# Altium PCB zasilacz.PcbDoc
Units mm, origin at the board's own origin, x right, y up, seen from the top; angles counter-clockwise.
Board outline 105.03 x 79.76 mm, 2 copper layers (Top Layer, Bottom Layer); 33 components, 30 nets, 109 pads, 1 vias.
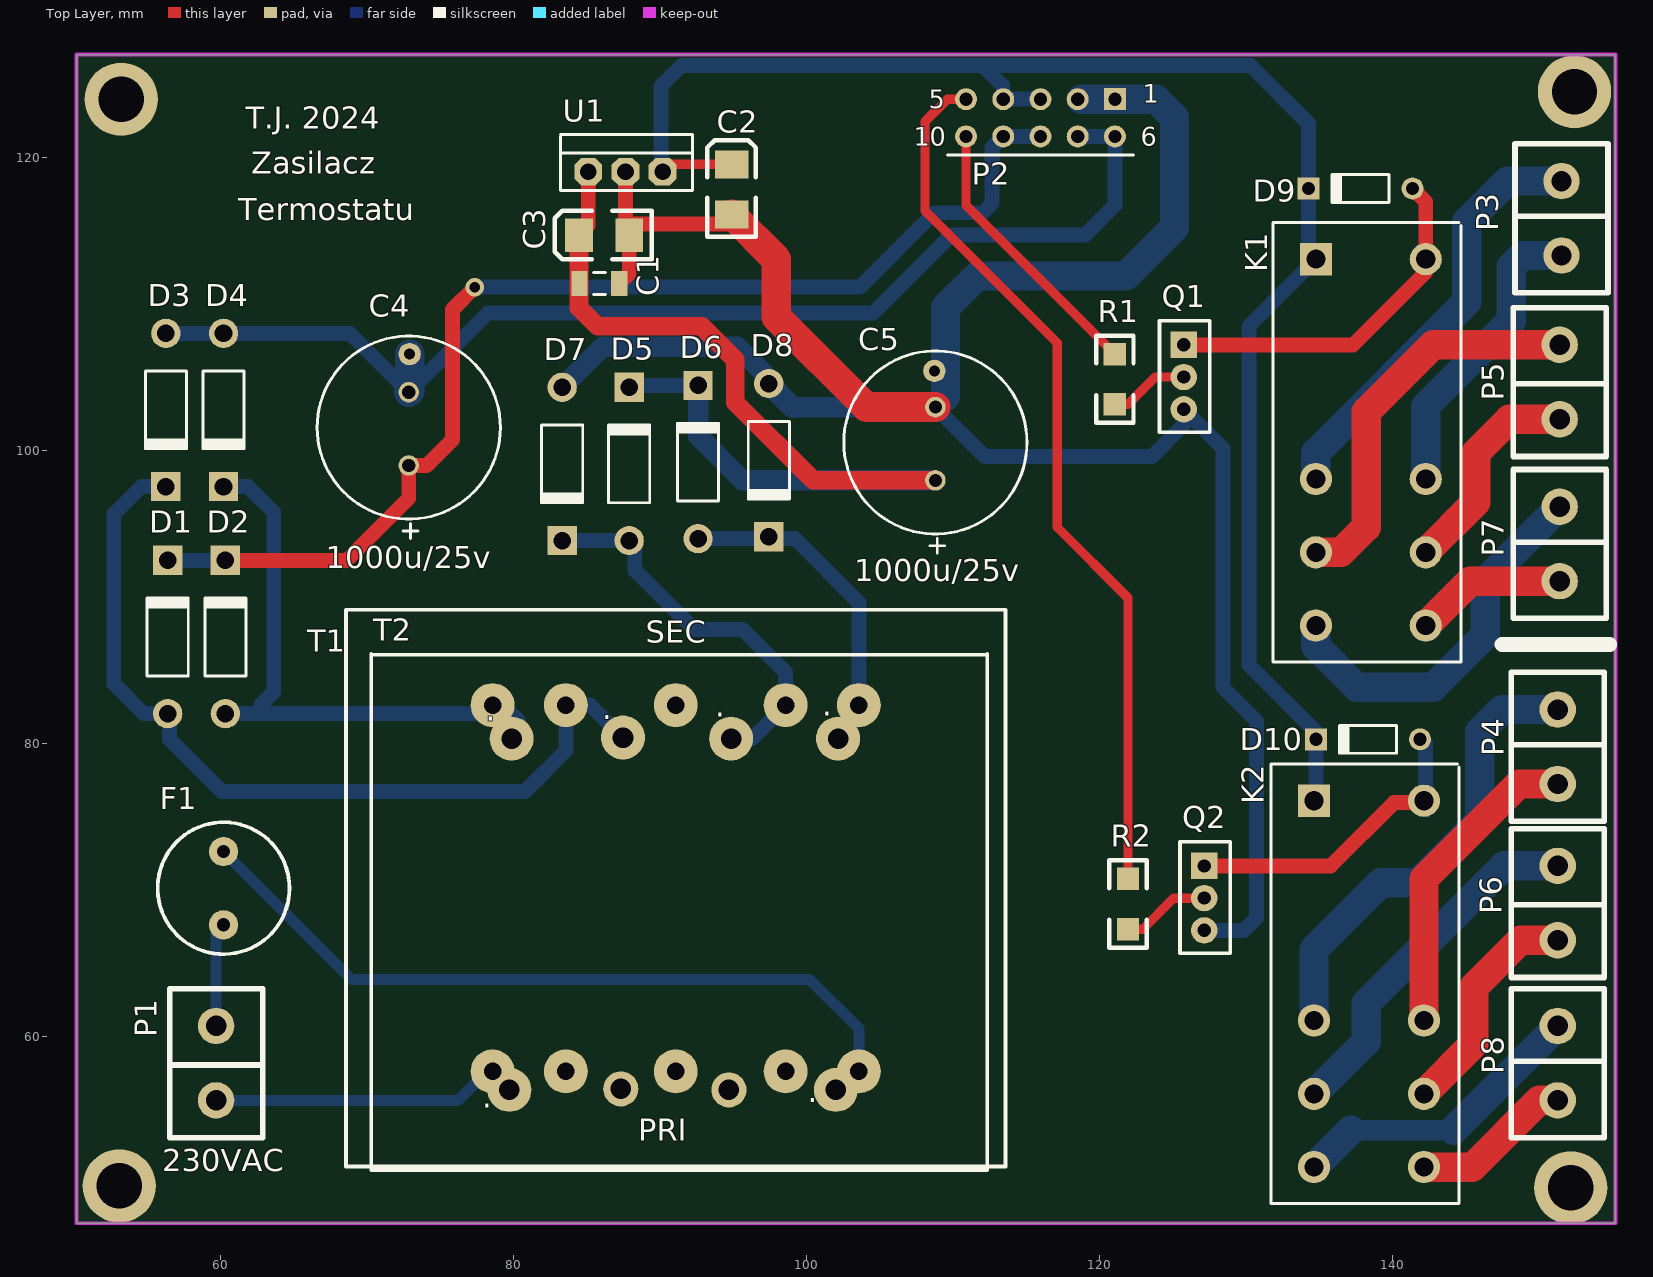
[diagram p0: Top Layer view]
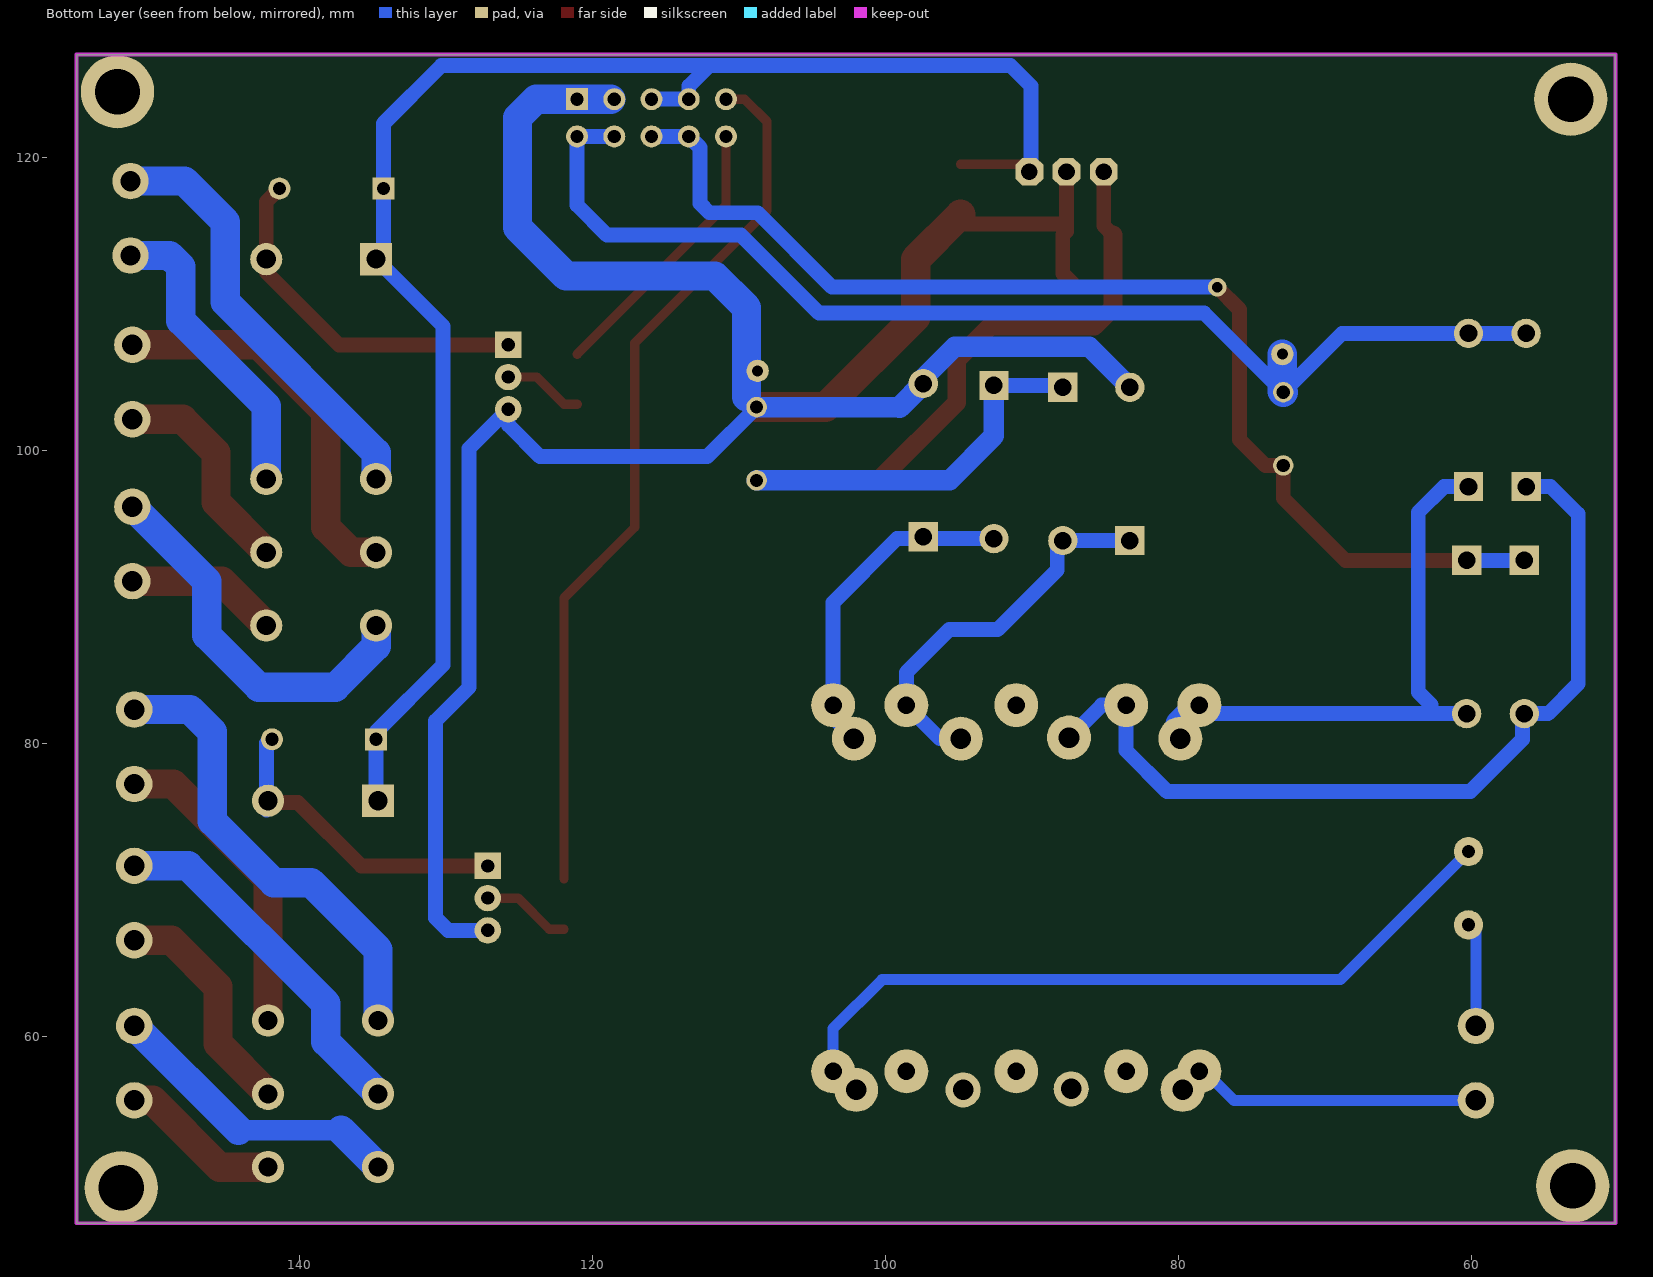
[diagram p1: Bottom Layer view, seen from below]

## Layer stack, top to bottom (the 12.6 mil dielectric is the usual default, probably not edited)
Top Solder: solder mask 0.0102, Solder Resist, Dk 3.5
Top Layer: signal copper 0.0356
Dielectric 1: dielectric 0.32, FR-4, Dk 4.8
Bottom Layer: signal copper 0.0356
Bottom Solder: solder mask 0.0102, Solder Resist, Dk 3.5

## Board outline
50.165,47.244 155.194,47.244 155.194,127 50.165,127

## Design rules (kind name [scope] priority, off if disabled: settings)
Clearance [All] p1: gap=0.254
PolygonConnect [All] p1: connectstyle=Relief reliefconductorwidth=0.254 reliefentries=4 polygonreliefangle="90 Angle" airgapwidth=0.254
RoutingVias [All] p1: holewidth=0.711 width=1.27 viastyle="Through Hole" minholewidth=0.711 minwidth=1.27 maxholewidth=0.711 maxwidth=1.27
SolderMaskExpansion [All] p1: expansion=0.102
Width [All] p1: maxlimit=2 minlimit=2 preferedwidth=2
30 further rules are at their usual default settings.

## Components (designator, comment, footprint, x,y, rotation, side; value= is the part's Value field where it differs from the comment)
C1 "Cap" C1206 85.852,111.379 r180 top
C2 "10u" 3528 94.869,119.507 r90 top
C3 "10u" 3528 84.455,114.681 r180 top
C4 "1000u/25v" 1000u/35v 73.025,101.346 r270 top
C5 "1000u/25v" 1000u/35v 108.966,100.33 r270 top
D1 "" DO-41 56.388,87.249 r90 top
D2 "" DO-41 60.325,87.249 r90 top
D3 "" DO-41 56.261,102.743 r270 top
D4 "" DO-41 60.198,102.743 r270 top
D5 "" DO-41 87.884,99.06 r90 top
D6 "" DO-41 92.583,99.187 r90 top
D7 "" DO-41 83.312,99.06 r270 top
D8 "" DO-41 97.409,99.314 r270 top
D9 "1N4148" DO-35 137.795,117.856 r180 top
D10 "1N4148" DO-35 138.303,80.264 r180 top
F1 "FUSE1" BEZP_OKR 60.198,70.104 r270 top
K1 "Relay-DPDT" Prz_big 134.747,113.03 r0 top
K2 "Relay-DPDT" Prz_big 134.62,76.073 r0 top
P1 "230VAC" ZLSRUB2-1 60.452,57.404 r90 top
P2 "Header 5X2A" HDR2X5_CEN 121.031,123.952 r180 top
P3 "Header 2" ZLSRUB2-1 150.749,116.586 r270 top
P4 "K1_O_NC" ZLSRUB2-1 150.495,80.518 r270 top
P5 "K2_IN" ZLSRUB2-1 152.146,103.886 r90 top
P6 "K1_IN" ZLSRUB2-1 152.019,68.326 r90 top
P7 "K2_O_NO" ZLSRUB2-1 150.622,94.361 r270 top
P8 "K1_O_NO" ZLSRUB2-1 150.495,58.928 r270 top
Q1 "NPN" BD139 125.73,107.188 r0 top
Q2 "NPN" BD139 127.127,71.628 r0 top
R1 "1K" 1206 121.031,106.553 r270 top
R2 "1K" 1206 121.92,70.739 r270 top
T1 "2x6V" "TRAFO ZZ7" 91.059,70.104 r180 top
T2 "" TRAFO_5W 90.297,69.088 r0 top
U1 "7805" 78XXST 85.725,119.38 r0 top

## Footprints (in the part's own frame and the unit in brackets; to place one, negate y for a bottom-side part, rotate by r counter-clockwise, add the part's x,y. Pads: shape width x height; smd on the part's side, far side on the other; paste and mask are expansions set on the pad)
78XXST [mil]
  oct 75x75 hole 45: 1(-25,-15) 2(75,-15) 3(175,-15)
  silkscreen extent -100,-65 255,85
1000u/35v [mm]
  round 1.4 hole 0.9: 1(2.392,-0.187) 2(-2.608,-0.187)
  silkscreen extent -6.44,-6.44 7.36,6.06
1206 [mil]
  rect 60x60 smd: 1(0,0) 2(135,0)
  silkscreen extent -50,-50 185,50
3528 [mil]
  rect 75x90 smd: 1(0,0) 2(-135,0)
  silkscreen extent -195,-65 65,65
BD139 [mm]
  rect 1.8x1.8 hole 0.9: 1(0,0)
  round 1.8 hole 0.9: 2(0,-2.2) 3(0,-4.4)
  silkscreen extent -1.65,-5.97 1.78,1.65
BEZP_OKR [mm]
  round 2 hole 0.9: 1(-2.5,0) 2(2.5,0)
  silkscreen extent -4.5,-4.5 4.5,4.5
C1206 [mm] "Chip Capacitor, Body 3.2x1.6mm, IPC High Density"
  rect 1.1x1.7 smd: 1(-1.35,0) 2(1.35,0)
  silkscreen extent -0.4,-0.75 0.4,0.75, body extent -1.7,-0.9 1.7,0.9, height 1.3
DO-35 [mm] "Diode, Axial; Body 3.8 x 1.9 mm (LxDia. max), Lead Dia. 0.53 mm (max)"
  round 1.5 hole 0.9: 1(-3.55,0)
  rect 1.5x1.5 hole 0.9: 2(3.55,0)
  silkscreen extent -1.95,-0.95 2.05,0.95
DO-41 [mm] "Diode, Axial; Body 5.2 x 2.7 mm (LxDia. max), Lead Dia. 0.86 mm (max)"
  round 2 hole 1.2: 1(-5.23,0)
  rect 2x2 hole 1.2: 2(5.23,0)
  silkscreen extent -2.65,-1.4 2.75,1.4
HDR2X5_CEN [mm] "Connector; Header; 5x2 Position"
  rect 1.5x1.5 hole 0.9: 1(0,0)
  round 1.5 hole 0.9: 2(2.54,0) 3(5.08,0) 4(7.62,0) 5(10.16,0) 6(0,2.54) 7(2.54,2.54) 8(5.08,2.54) 9(7.62,2.54) 10(10.16,2.54)
  silkscreen extent -1.27,3.81 11.43,3.81
Prz_big [mm]
  round 2.2 hole 1.3: 1(0,-20) 2(0,-15) 3(0,-25) 4(7.5,-20) 5(7.5,-15) 6(7.5,-25) 8(7.5,0)
  rect 2.2x2.2 hole 1.3: 7(0,0)
  silkscreen extent -2.92,-27.5 9.91,2.5
"TRAFO ZZ7" [mm]
  round 3 hole 1.2: 1(-12.5,12.5) 2(-7.5,12.5) 3(0,12.5) 4(7.5,12.5) 5(12.5,12.5) 6(12.5,-12.5) 7(7.5,-12.5) 8(0,-12.5) 9(-7.5,-12.5) 10(-12.5,-12.5)
  silkscreen extent -22.5,-19 22.5,19
TRAFO_5W [mm]
  round 3 hole 1.4: 1(11.688,-12.752) 5(-10.587,-12.752) 6(-10.437,11.223) 7(-2.837,11.298) 9(4.538,11.223) 10(11.838,11.223)
  round 2.4 hole 1.4: 2(4.388,-12.752) 4(-2.987,-12.677)
  silkscreen extent -20.02,-18.23 22.02,17.02
ZLSRUB2-1 [mil]
  round 98 hole 55: 1(-70,30) 2(130,30)
  silkscreen extent -170,-95 230,155

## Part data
C1: "Capacitor"
C2 C3 C4 C5: library part ELECTRO2, "Electrolytic Capacitor"
D1 D2 D3 D4 D5 D6 D7 D8: library part "Diode 1N4007", "1 Amp General Purpose Rectifier"
D9 D10: library part "Diode 1N4148", "High Conductance Fast Diode"
F1: "Fuse"
K1 K2: "Dual-Pole Dual-Throw Relay"
P1 P4 P5 P6 P7 P8: library part "Header 2", "Header, 2-Pin"
P2: "Header, 5-Pin, Dual row"
P3: "Header, 2-Pin"
Q1 Q2: "NPN Bipolar Transistor"
R1 R2: library part Res2, "Resistor"
T1: library part "trafo ZZ2"
U1: library part 78XX

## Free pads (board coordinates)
  round 5 hole 3.1: 0(53.086,49.784) 0(53.213,123.952) 0(152.146,49.657) 0(152.4,124.46)
  round 1.524 hole 0.762: 0(72.898,106.553) 1(108.712,105.41)

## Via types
v1: diameter 1.27, hole 0.711, Top Layer to Bottom Layer, 1 vias

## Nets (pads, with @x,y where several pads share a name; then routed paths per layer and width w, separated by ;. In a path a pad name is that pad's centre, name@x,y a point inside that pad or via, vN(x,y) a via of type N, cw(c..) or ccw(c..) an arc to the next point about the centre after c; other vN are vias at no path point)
+5VD: C2.1 D9.2 D10.2 K1.7 K2.7 P2.3 P2.4 U1.3 | length 112.8
  Top Layer w0.635: U1.3 90.678,119.507 C2.1
  Bottom Layer w1.016: U1.3@90.043,118.745 90.043,124.841 91.44,126.238 112.014,126.238 ; P2.3 P2.4 113.411,124.841 112.014,126.238 ; K2.7@134.753,76.327 134.753,80.766 130.175,85.344 130.175,108.458 K1.7 134.245,113.532 D9.2 134.245,122.295 130.302,126.238 112.014,126.238
+VDD: C1.2 C3.1 C5.1 D5.2 D6.2 U1.1 | length 66.1
  Top Layer w1.016: C3.1 85.09,115.316 U1.1
  Top Layer w1.27: C3.1 84.455,109.728 85.725,108.458 92.837,108.458 95.123,106.172 95.123,103.251 100.436,97.938 C5.1
  Bottom Layer w1.016: D5.2 88.011,104.417 D6.2
  Bottom Layer w1.397: D6.2 92.583,100.965 95.61,97.938 C5.1
+VDD1: C4.1 D1.2 D2.2 P2.8 P2.9 | length 80.3
  Top Layer w1.016: D2.2 68.603,92.479 72.838,96.714 C4.1 74.062,98.954 75.819,100.711 75.819,109.601 v1(77.343,111.125)
  Bottom Layer w1.016: D1.2 D2.2 ; v1(77.343,111.125) 103.632,111.125 108.712,116.205 112.014,116.205 112.649,116.84 112.649,120.65 P2.9 P2.8
GND: C1.1 C2.2 C3.2 C5.2 D7.1 D8.1 P2.1 P2.2 pad.1 Q1.3 Q2.3 U1.2 | length 165.8
  Top Layer w1.016: C1.1 87.884,112.061 C3.2 ; U1.2 87.63,114.935 88.138,115.443 C2.2@95.123,115.443
  Top Layer w2.032: C2.2 97.917,113.03 97.917,109.093 104.072,102.938 C5.2
  Bottom Layer w1.016: D8.1 D8.1@97.409,104.902 ; 109.474,103.633 C5.2 112.149,99.568 123.571,99.568 125.73,101.727 Q1.3 128.397,100.121 128.397,83.82 130.683,81.534 130.683,68.072 129.839,67.228 Q2.3
  Bottom Layer w1.397: D7.1 86.083,107.061 95.25,107.061 D8.1@97.409,104.902 ; 99.015,102.938 C5.2
  Bottom Layer w1.5: D8.1 99.015,102.938
  Bottom Layer w2: 109.474,103.633 109.474,109.728 111.633,111.887 121.793,111.887 125.095,115.189 125.095,122.682 123.825,123.952 P2.2@118.745,123.952
GND1: C4.2 D3.1 D4.1 P2.6 P2.7 pad.0@72.898,106.553 | length 81.5
  Bottom Layer w1.016: D3.1 D4.1 68.819,107.973 C4.2 ; C4.2@72.898,104.014 78.231,109.347 104.521,109.347 109.855,114.681 118.999,114.681 121.031,116.713 P2.6 P2.7
  Bottom Layer w2: C4.2 72.898,104.014 pad.0@72.898,106.553
NetD1_1: D1.1 D3.2 T1.7 T2.7 | length 59.8
  Bottom Layer w1: T1.7 85.242,82.604 T2.7
  Bottom Layer w1.016: D3.2 54.587,97.513 52.705,95.631 52.705,84.074 54.76,82.019 D1.1 56.515,81.892 56.515,80.264 60.071,76.708 80.772,76.708 83.559,79.495 T1.7
NetD2_1: D2.1 D4.2 T1.6 T2.6 | length 39
  Bottom Layer w1.016: D4.2 61.872,97.513 63.627,95.758 63.627,83.493 62.738,82.604 ; D2.1 77.974,82.019 T1.6
  Bottom Layer w2: T1.6 79.86,81.303 T2.6
NetD5_1: D5.1 D7.2 T1.9 T2.9 | length 26.8
  Bottom Layer w1: T2.9 96.266,80.311 T1.9
  Bottom Layer w1.016: D7.2 D5.1 88.265,93.449 88.265,91.821 92.329,87.757 95.631,87.757 98.559,84.829 T1.9
NetD6_1: D6.1 D8.2 T1.10 T2.10 | length 22.7
  Bottom Layer w1: T2.10 103.559,81.735 T1.10
  Bottom Layer w1.016: D6.1 99.21,93.957 103.559,89.608 T1.10
NetD9_1: D9.1 K1.8 Q1.1 | length 24.7
  Top Layer w1.016: Q1.1 137.287,107.188 142.247,112.148 K1.8 142.247,116.954 D9.1
NetD10_1: D10.1 K2.8 Q2.1 | length 21.3
  Top Layer w1.016: Q2.1 135.763,71.628 140.081,75.946 142.107,75.946 K2.8@142.12,75.933
  Bottom Layer w1.016: K2.8@142.234,75.451 D10.1@142.234,80.01
NetF1_1: F1.1 T1.1 T2.1 | length 51.3
  Bottom Layer w0.762: F1.1 68.921,63.881 100.203,63.881 103.559,60.525 T1.1
NetF1_2: F1.2 P1.2 | length 7.1
  Bottom Layer w0.762: P1.2 59.69,67.096 F1.2
NetK1_1: K1.1 P5.2 | length 27.1
  Top Layer w2: K1.1 136.464,93.03 138.176,94.742 138.176,102.616 142.748,107.188 P5.2
NetK1_2: K1.2 P3.1 | length 29.4
  Bottom Layer w2: K1.2 134.747,99.822 145.034,110.109 145.034,115.57 147.828,118.364 P3.1
NetK1_3: K1.3 P7.1 | length 26.5
  Bottom Layer w2: K1.3 134.747,86.614 137.541,83.82 142.748,83.82 146.304,87.376 146.304,91.059 P7.1
NetK1_4: K1.4 P5.1 | length 14.9
  Top Layer w2: K1.4 145.669,96.452 145.669,99.822 147.955,102.108 P5.1
NetK1_5: K1.5 P3.2 | length 20.7
  Bottom Layer w2: K1.5 142.247,103.004 148.082,108.839 148.082,112.522 148.844,113.284 P3.2
NetK1_6: K1.6 P7.2 | length 10.4
  Top Layer w2: K1.6 142.259,88.03 145.288,91.059 P7.2
NetK2_1: K2.1 P6.2 | length 24.6
  Bottom Layer w2: K2.1 138.176,59.629 138.176,62.23 147.574,71.628 P6.2
NetK2_2: K2.2 P4.1 | length 31.8
  Bottom Layer w2: K2.2 134.62,65.913 139.192,70.485 141.732,70.485 145.923,74.676 145.923,80.772 147.447,82.296 P4.1
NetK2_3: K2.3 P8.1 | length 20.6
  Bottom Layer w1.4: 137.141,53.594 144.145,53.594
  Bottom Layer w2: K2.3 137.141,53.594 ; 144.145,53.594 P8.1
NetK2_4: K2.4 P6.1 | length 15.7
  Top Layer w2: K2.4 145.542,59.495 145.542,63.373 148.717,66.548 P6.1
NetK2_5: K2.5 P4.2 | length 21.5
  Top Layer w2: K2.5 142.12,70.746 148.59,77.216 P4.2
NetK2_6: K2.6 P8.2 | length 11
  Top Layer w2: K2.6 142.139,51.054 145.415,51.054 149.987,55.626 P8.2
NetP1_1: P1.1 T1.5 T2.5 | length 19.7
  Bottom Layer w0.762: P1.1 76.2,55.626 78.178,57.604 T1.5
NetQ1_2: Q1.2 R1.2 | length 5.5
  Top Layer w0.635: R1.2 121.92,103.124 123.784,104.988 Q1.2
NetQ2_2: Q2.2 R2.2 | length 6.1
  Top Layer w0.635: R2.2 122.936,67.31 125.054,69.428 Q2.2
STER1: P2.5 R2.1 | length 60.8
  Top Layer w0.635: P2.5 109.601,123.952 108.077,122.428 108.077,116.332 117.094,107.315 117.094,94.742 121.92,89.916 R2.1
STER2: P2.10 R1.1 | length 19.1
  Top Layer w0.635: P2.10 110.871,116.713 R1.1
pads on no net: T1.2 T1.3 T1.4 T1.8 T2.2 T2.4

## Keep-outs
Keep-Out Layer:
  the board outline again, w0.254

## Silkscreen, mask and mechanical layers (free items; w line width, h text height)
Top Overlay:
  lines w1: 147.447,86.741 154.813,86.741
  text "T.J. 2024" at 61.722,121.92 h1.52
  text "Zasilacz" at 62.103,118.872 h1.52
  text "Termostatu" at 61.214,115.697 h1.52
